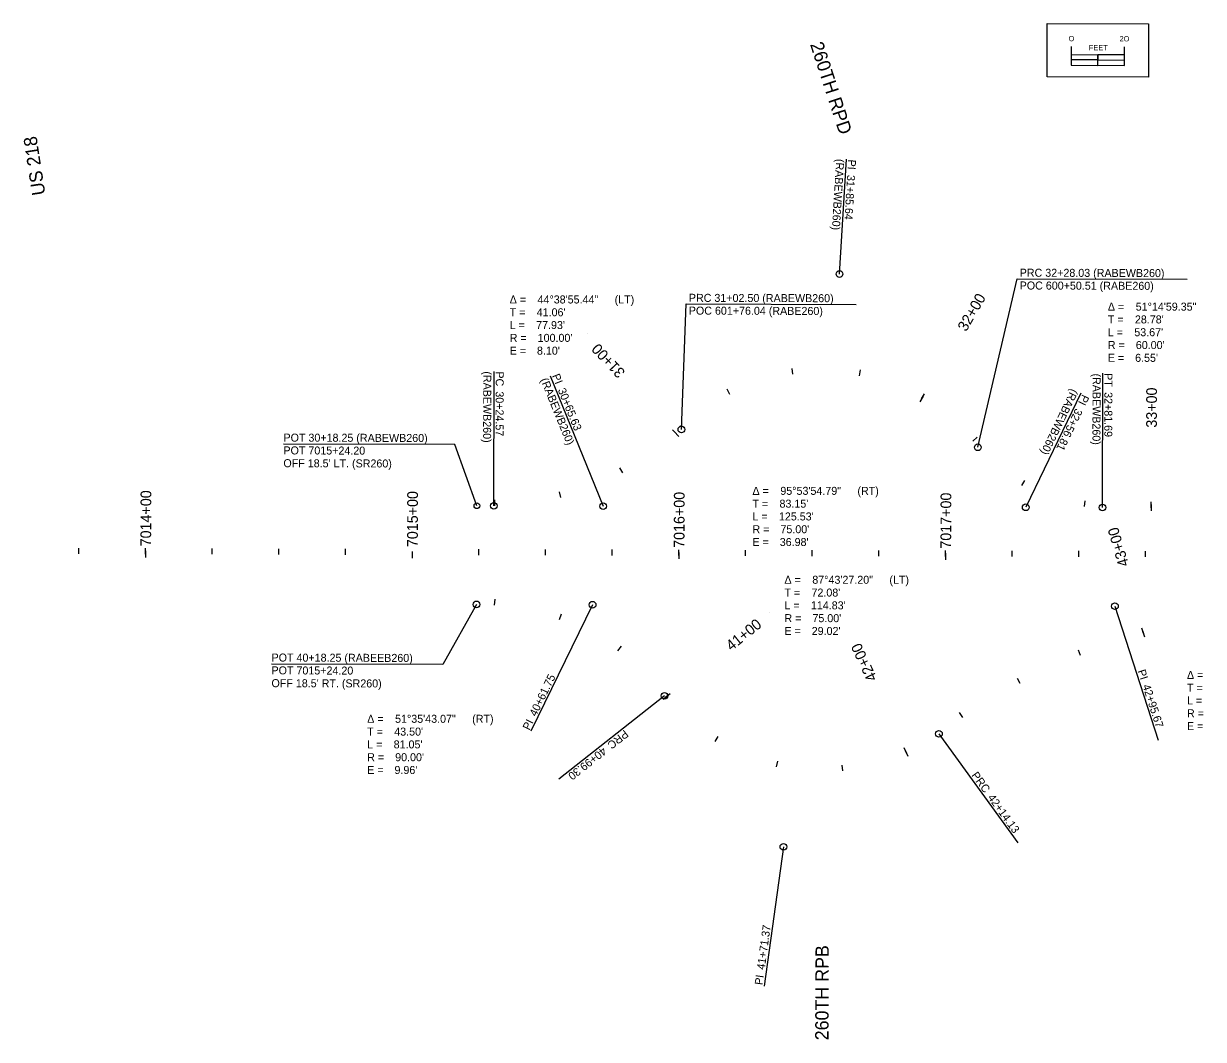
# Model space of a CAD drawing. Extents: x 5195296 to 5198948, y 3709168 to 3709552.
# Drawn here: x 5197152.1 to 5197594.5, y 3709168.4 to 3709549.4 of the extents above; entities that cross this region are included whole.
import ezdxf

# ---------------------------------------------------------------- set-up
doc = ezdxf.new("R2010")
doc.units = 0
for name, color, linetype in [('dsnAlignmentStation', 7, 'Continuous'), ('dsnGeopakCellProfile', 7, 'Continuous'), ('dsnProfileEntranceGradeProp', 7, 'Continuous')]:
    doc.layers.add(name, color=color, linetype=linetype)

msp = doc.modelspace()

# ---------------------------------------------------------------- linework, layer by layer
at = {"layer": 'dsnAlignmentStation'}
for p, q in [((5197172.84, 3709350.51), (5197172.84, 3709352.69)), ((5197222.84, 3709350.36), (5197222.84, 3709352.54)), ((5197247.84, 3709350.29), (5197247.84, 3709352.47)), ((5197272.84, 3709350.22), (5197272.84, 3709352.4)), ((5197322.84, 3709350.07), (5197322.84, 3709352.26)), ((5197197.84, 3709351.66), (5197197.83, 3709349.21)), ((5197297.84, 3709351.37), (5197297.83, 3709348.92)), ((5197347.83, 3709350), (5197347.84, 3709352.18)), ((5197372.83, 3709349.93), (5197372.84, 3709352.11)), ((5197397.84, 3709351.08), (5197397.83, 3709348.63)), ((5197422.83, 3709349.78), (5197422.84, 3709351.97)), ((5197447.83, 3709349.71), (5197447.84, 3709351.89)), ((5197472.83, 3709349.64), (5197472.84, 3709351.82)), ((5197497.84, 3709350.79), (5197497.83, 3709348.34)), ((5197522.83, 3709349.49), (5197522.84, 3709351.68)), ((5197547.83, 3709349.42), (5197547.84, 3709351.61)), ((5197572.83, 3709349.35), (5197572.84, 3709351.53))]:
    msp.add_line(p, q, dxfattribs=at)
at = {"layer": 'dsnGeopakCellProfile'}
for p, q in [((5197554.94, 3709533.73), (5197554.95, 3709537.73)), ((5197554.94, 3709533.73), (5197554.95, 3709537.73)), ((5197458.09, 3709455.47), (5197460.7, 3709498.51)), ((5197460.7, 3709498.51), (5197460.7, 3709498.51)), ((5197363.45, 3709433.17), (5197363.45, 3709433.17)), ((5197328.41, 3709368.56), (5197328.56, 3709418.96)), ((5197328.56, 3709418.96), (5197328.56, 3709418.96)), ((5197440.63, 3709417.94), (5197440.32, 3709420.1)), ((5197465.51, 3709417.35), (5197465.93, 3709419.49)), ((5197349.56, 3709417.34), (5197369.47, 3709368.44)), ((5197556.68, 3709367.9), (5197556.82, 3709418.3)), ((5197416.93, 3709410.35), (5197415.93, 3709412.29)), ((5197489.44, 3709409.71), (5197488.22, 3709407.59)), ((5197488.83, 3709408.65), (5197489.92, 3709410.54)), ((5197548.6, 3709410.83), (5197527.9, 3709367.98)), ((5197396.97, 3709395.48), (5197395.48, 3709397.08)), ((5197359.52, 3709392.89), (5197359.52, 3709392.89)), ((5197396.13, 3709396.38), (5197397.8, 3709394.59)), ((5197508.01, 3709392.8), (5197509.66, 3709394.23)), ((5197376.77, 3709380.87), (5197375.72, 3709382.78)), ((5197526.46, 3709376.16), (5197527.56, 3709378.05)), ((5197328.84, 3709368.56), (5197328.84, 3709370.74)), ((5197353.58, 3709371.7), (5197353.03, 3709373.81)), ((5197550, 3709368.29), (5197550.25, 3709370.46)), ((5197574.98, 3709367.84), (5197574.99, 3709370.03)), ((5197574.98, 3709369.07), (5197574.98, 3709366.62)), ((5197328.73, 3709331.3), (5197328.9, 3709333.48)), ((5197365.49, 3709331.45), (5197342.37, 3709283.98)), ((5197561.37, 3709330.88), (5197577.59, 3709280.64)), ((5197353.06, 3709325.94), (5197353.82, 3709327.99)), ((5197432, 3709328.47), (5197432, 3709328.47)), ((5197572.09, 3709320.62), (5197571.48, 3709322.72)), ((5197571.75, 3709321.8), (5197572.43, 3709319.45)), ((5197375, 3709314.11), (5197376.29, 3709315.87)), ((5197548.48, 3709312.42), (5197547.66, 3709314.45)), ((5197525.81, 3709301.91), (5197524.8, 3709303.84)), ((5197392.41, 3709297.28), (5197352.83, 3709266.08)), ((5197393.81, 3709297.5), (5197391.9, 3709295.96)), ((5197392.85, 3709296.73), (5197394.56, 3709298.1)), ((5197504.3, 3709289.19), (5197503.1, 3709291.01)), ((5197411.44, 3709280.18), (5197412.6, 3709282.03)), ((5197495.37, 3709283), (5197524.96, 3709242.2)), ((5197483.22, 3709275.82), (5197482.29, 3709277.8)), ((5197434.42, 3709270.63), (5197434.91, 3709272.76)), ((5197482.7, 3709276.93), (5197483.74, 3709274.71)), ((5197459.26, 3709269.12), (5197459.03, 3709271.29)), ((5197524.96, 3709242.2), (5197524.96, 3709242.2)), ((5197437.03, 3709240.67), (5197429.77, 3709188.37)), ((5197429.77, 3709188.37), (5197429.77, 3709188.37))]:
    msp.add_line(p, q, dxfattribs=at)
for points in [[(5197535.99, 3709549.38), (5197573.99, 3709549.27), (5197573.93, 3709529.27), (5197535.93, 3709529.38)], [(5197535.99, 3709549.38), (5197573.99, 3709549.27), (5197573.93, 3709529.27), (5197535.93, 3709529.38)], [(5197544.94, 3709533.76), (5197554.94, 3709533.73), (5197554.95, 3709535.74), (5197544.95, 3709535.77)], [(5197554.95, 3709535.74), (5197564.95, 3709535.71), (5197564.95, 3709537.7), (5197554.95, 3709537.73)]]:
    msp.add_lwpolyline(points, close=True, dxfattribs=at)
for points in [[(5197544.96, 3709540.76), (5197544.94, 3709533.76), (5197564.94, 3709533.7), (5197564.96, 3709540.7)], [(5197544.95, 3709537.76), (5197564.95, 3709537.7)], [(5197509.95, 3709390.48), (5197524.68, 3709453.66), (5197588.42, 3709453.48)], [(5197398.77, 3709397.21), (5197400.6, 3709444.24), (5197464.34, 3709444.06)], [(5197322.09, 3709368.57), (5197313.84, 3709391.56), (5197249.56, 3709391.62)], [(5197321.98, 3709331.57), (5197309.37, 3709309.07), (5197245.09, 3709309.13)]]:
    msp.add_lwpolyline(points, dxfattribs=at)
for centre, radius in [((5197458.09, 3709455.47), 1.25), ((5197398.77, 3709397.21), 1.25), ((5197398.77, 3709397.21), 1.25), ((5197509.95, 3709390.48), 1.25), ((5197509.95, 3709390.48), 1.25), ((5197322.09, 3709368.57), 1.07), ((5197328.41, 3709368.56), 1.25), ((5197369.47, 3709368.44), 1.25), ((5197527.9, 3709367.98), 1.25), ((5197556.68, 3709367.9), 1.25), ((5197321.98, 3709331.57), 1.25), ((5197365.49, 3709331.45), 1.25), ((5197561.37, 3709330.88), 1.25), ((5197392.41, 3709297.28), 1.25), ((5197392.41, 3709297.28), 1.25), ((5197495.37, 3709283), 1.25), ((5197495.37, 3709283), 1.25), ((5197437.03, 3709240.67), 1.25)]:
    msp.add_circle(centre, radius, dxfattribs=at)
at = {"layer": 'dsnProfileEntranceGradeProp'}
for p, q in [((5197197.84, 3709350.43), (5197197.84, 3709352.62)), ((5197297.84, 3709351.37), (5197297.83, 3709348.92)), ((5197397.83, 3709349.86), (5197397.84, 3709352.04)), ((5197497.83, 3709349.57), (5197497.84, 3709351.75))]:
    msp.add_line(p, q, dxfattribs=at)

# ---------------------------------------------------------------- texts
at = {"layer": 'dsnAlignmentStation'}
for s, p in [('7014+00', (5197199.93, 3709353.34)), ('7015+00', (5197299.93, 3709353.05)), ('7016+00', (5197399.93, 3709352.76)), ('7017+00', (5197499.93, 3709352.47))]:
    msp.add_text(s, height=4.008, rotation=89.8345, dxfattribs=at).set_placement(p)
at = {"layer": 'dsnGeopakCellProfile'}
for s, height, rotation, p in [('260TH RPD', 5, 288.0738, (5197446.98, 3709541.61)), ('O', 2, 359.8345, (5197543.98, 3709542.76)), ('2O', 2, 359.8345, (5197563.09, 3709542.71)), ('FEET', 2, 359.8345, (5197551.57, 3709539.34)), ('US 218', 5, 98.6831, (5197160.31, 3709485.36)), ('(RABEWB260)', 3, 266.5339, (5197456.83, 3709498.71)), ('PI ', 3, 266.5339, (5197461.3, 3709498.48)), ('31+85.64', 3, 266.5339, (5197460.95, 3709492.69)), ('PRC 32+28.03 (RABEWB260)', 3, 359.8345, (5197525.64, 3709454.47)), ('POC 600+50.51 (RABE260)', 3, 359.8345, (5197525.63, 3709449.67)), ('PRC 31+02.50 (RABEWB260)', 3, 359.8345, (5197401.57, 3709445.05)), ('32+00', 4.008, 59.9949, (5197505.57, 3709433.63)), ('POC 601+76.04 (RABE260)', 3, 359.8345, (5197401.55, 3709440.25)), ('31+00', 4.008, 133.0536, (5197377.95, 3709418.77)), ('(RABEWB260)', 3, 269.8345, (5197324.5, 3709418.98)), ('PC', 3, 269.8345, (5197329.16, 3709418.95)), ('(RABEWB260)', 3, 292.1588, (5197345.87, 3709415.81)), ('PI ', 3, 292.1588, (5197350.21, 3709417.35)), ('(RABEWB260)', 3, 269.8345, (5197552.99, 3709418.16)), ('PT', 3, 269.8345, (5197557.43, 3709418.29)), ('30+24.57', 3, 269.8345, (5197329.14, 3709411.47)), ('30+65.63', 3, 292.1588, (5197352.39, 3709411.98)), ('(RABEWB260)', 3, 244.2095, (5197545.02, 3709412.63)), ('PI ', 3, 244.2095, (5197549.14, 3709410.54)), ('32+81.69', 3, 269.8345, (5197557.41, 3709411.18)), ('33+00', 4.008, 89.8345, (5197577.07, 3709397.84)), ('32+56.81', 3, 244.2095, (5197546.62, 3709405.32)), ('POT 30+18.25 (RABEWB260)', 3, 359.8345, (5197249.56, 3709392.63)), ('POT 7015+24.20', 3, 359.8345, (5197249.54, 3709387.83)), ("OFF 18.5' LT. (SR260)", 3, 359.8345, (5197249.53, 3709383.03)), ('43+00', 4.008, 106.2826, (5197566.65, 3709346.39)), ('41+00', 4.008, 38.7772, (5197417.5, 3709313.96)), ('42+00', 4.008, 115.1716, (5197472.28, 3709303.83)), ('POT 40+18.25 (RABEEB260)', 3, 359.8345, (5197245.09, 3709310.14)), ('POT 7015+24.20', 3, 359.8345, (5197245.07, 3709305.34)), ("OFF 18.5' RT. (SR260)", 3, 359.8345, (5197245.06, 3709300.54)), ('40+61.75', 3, 64.0368, (5197344.3, 3709289.31)), ('PI ', 3, 287.8989, (5197569.84, 3709306.62)), ('42+95.67', 3, 287.8989, (5197571.64, 3709301.05)), ('PI ', 3, 64.0368, (5197341.78, 3709284.15)), ('PRC', 3, 218.2392, (5197377.41, 3709284.68)), ('40+99.30', 3, 218.2392, (5197369.25, 3709278.25)), ('PRC', 3, 305.9634, (5197507.39, 3709267.46)), ('42+14.13', 3, 305.9634, (5197513.49, 3709259.05)), ('41+71.37', 3, 82.1013, (5197430, 3709194.44)), ('260TH RPB', 5, 89.8345, (5197453.95, 3709168.1)), ('PI ', 3, 82.1013, (5197429.2, 3709188.7))]:
    msp.add_text(s, height=height, rotation=rotation, dxfattribs=at).set_placement(p)
for s, p in [('Δ = ', (5197334.39, 3709444.43)), ('44°38\'55.44"', (5197344.84, 3709444.43)), (' (LT)', (5197372.63, 3709444.43)), ('T = ', (5197334.39, 3709439.63)), ("41.06'", (5197344.53, 3709439.63)), ('Δ = ', (5197558.7, 3709441.74)), ('51°14\'59.35"', (5197569.15, 3709441.74)), ('L = ', (5197334.39, 3709434.83)), ("77.93'", (5197344.31, 3709434.83)), ('T = ', (5197558.7, 3709436.94)), ("28.78'", (5197568.84, 3709436.94)), ('R = ', (5197334.39, 3709430.03)), ("100.00'", (5197344.88, 3709430.03)), ('L = ', (5197558.7, 3709432.14)), ("53.67'", (5197568.62, 3709432.14)), ('E = ', (5197334.39, 3709425.23)), ("8.10'", (5197344.62, 3709425.23)), ('R = ', (5197558.7, 3709427.34)), ("60.00'", (5197569.19, 3709427.34)), ('E = ', (5197558.7, 3709422.54)), ("6.55'", (5197568.93, 3709422.54)), ('Δ = ', (5197425.43, 3709372.66)), ('95°53\'54.79"', (5197435.88, 3709372.66)), (' (RT)', (5197463.67, 3709372.66)), ('T = ', (5197425.43, 3709367.86)), ("83.15'", (5197435.57, 3709367.86)), ('L = ', (5197425.43, 3709363.06)), ("125.53'", (5197435.35, 3709363.06)), ('R = ', (5197425.43, 3709358.26)), ("75.00'", (5197435.92, 3709358.26)), ('E = ', (5197425.43, 3709353.46)), ("36.98'", (5197435.66, 3709353.46)), ('Δ = ', (5197437.42, 3709339.31)), ('87°43\'27.20"', (5197447.87, 3709339.31)), (' (LT)', (5197475.67, 3709339.31)), ('T = ', (5197437.42, 3709334.51)), ("72.08'", (5197447.56, 3709334.51)), ('L = ', (5197437.42, 3709329.71)), ("114.83'", (5197447.34, 3709329.71)), ('R = ', (5197437.42, 3709324.91)), ("75.00'", (5197447.92, 3709324.91)), ('E = ', (5197437.42, 3709320.11)), ("29.02'", (5197447.65, 3709320.11)), ('Δ = ', (5197588.37, 3709303.64)), ('T = ', (5197588.37, 3709298.84)), ('L = ', (5197588.37, 3709294.04)), (' (RT)', (5197319.21, 3709287.17)), ('R = ', (5197588.37, 3709289.24)), ('Δ = ', (5197280.96, 3709287.17)), ('51°35\'43.07"', (5197291.41, 3709287.17)), ('E = ', (5197588.37, 3709284.44)), ('T = ', (5197280.96, 3709282.37)), ("43.50'", (5197291.1, 3709282.37)), ('L = ', (5197280.96, 3709277.57)), ("81.05'", (5197290.88, 3709277.57)), ('R = ', (5197280.96, 3709272.77)), ("90.00'", (5197291.45, 3709272.77)), ('E = ', (5197280.96, 3709267.97)), ("9.96'", (5197291.19, 3709267.97))]:
    msp.add_text(s, height=3, dxfattribs=at).set_placement(p)
at = {"layer": 'dsnProfileEntranceGradeProp'}
msp.add_text('7015+00', height=4.008, rotation=89.8345, dxfattribs=at).set_placement((5197299.93, 3709353.05))

doc.saveas('drawing.dxf')
